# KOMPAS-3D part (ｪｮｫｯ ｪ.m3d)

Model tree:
1. Эскиз:1
2. Операция выдавливания:1
     Расстояние 1 = 30
3. Эскиз:2
4. Вырезать элемент выдавливания:1
     Расстояние 1 = 63
5. Эскиз:3
6. Операция выдавливания:2
     Расстояние 1 = 1
7. Эскиз:4
8. Вырезать элемент выдавливания:2
     Расстояние 1 = 2
9. Скругление:1
     Радиус = 1
10. Эскиз:5
11. Вырезать элемент выдавливания:3
     Расстояние 1 = 2
12. Эскиз:6
13. Вырезать элемент выдавливания:4
     Расстояние 1 = 2
